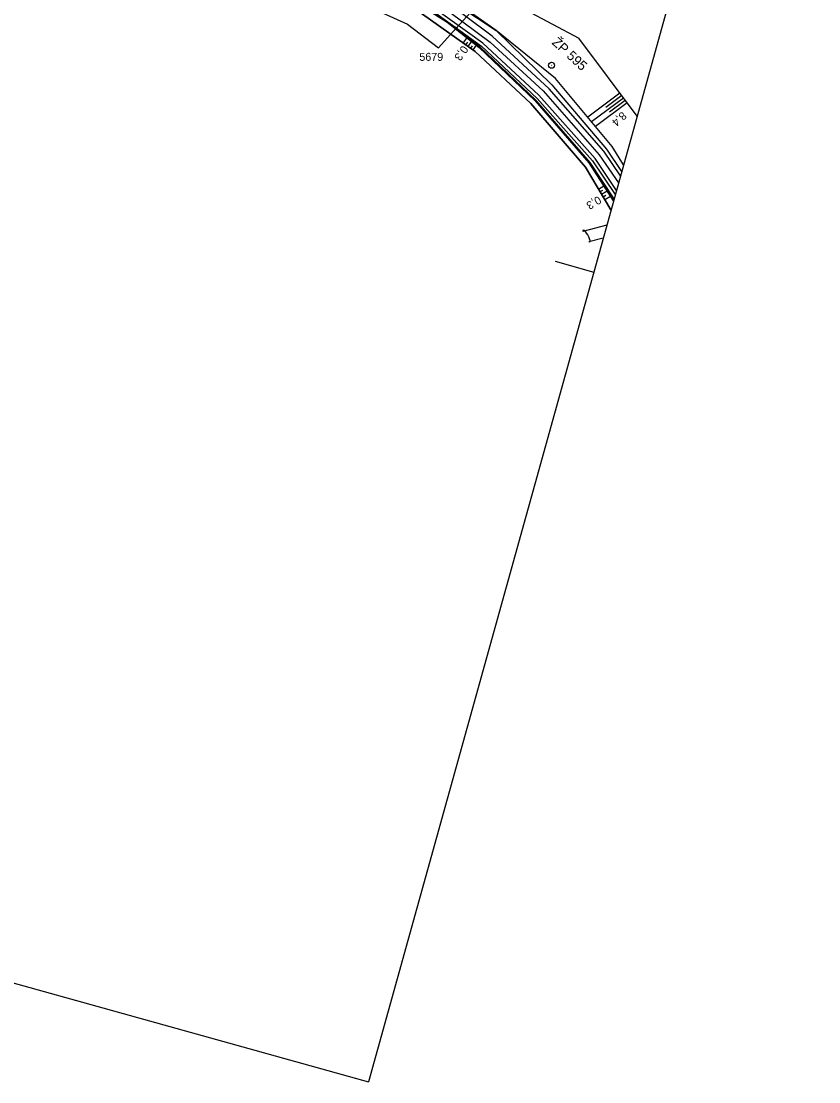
# Model space of a CAD drawing. Extents: x -795046 to -794647, y -1136002 to -1135518.
# Drawn here: x -794846.5 to -794647.1, y -1136002.2 to -1135737.2 of the extents above; entities that cross this region are included whole.
import ezdxf

# ---------------------------------------------------------------- set-up
doc = ezdxf.new("R2010")
doc.units = 0
for name, color, linetype in [('0381KM005-009P - Vrstva 1', 7, 'Continuous'), ('0381KM005-009P - Vrstva 13', 7, 'Continuous'), ('0381KM005-009P - Vrstva 18', 7, 'Continuous'), ('0381KM005-009P - Vrstva 4', 7, 'Continuous'), ('0381KM005-009P - Vrstva 48', 7, 'Continuous'), ('0381KM005-009P - Vrstva 49', 7, 'Continuous'), ('0381KM005-009P - Vrstva 51', 7, 'Continuous'), ('0381KM005-009P - Vrstva 55', 7, 'Continuous'), ('formát', 7, 'Continuous'), ('szdc - hran DP', 7, 'Continuous'), ('szdc - szdc_cislo', 7, 'Continuous'), ('szdc - szdc_krizek', 7, 'Continuous'), ('vyt_sit - stávající', 7, 'Continuous')]:
    doc.layers.add(name, color=color, linetype=linetype)

msp = doc.modelspace()

# ---------------------------------------------------------------- linework, layer by layer
at = {"layer": '0381KM005-009P - Vrstva 1'}
msp.add_lwpolyline([(-794915, -1135523.08), (-794913.46, -1135539.92), (-794911.29, -1135554.01), (-794906.18, -1135575.42), (-794898.43, -1135596.89), (-794896.25, -1135601.39), (-794889.11, -1135615.73), (-794881.58, -1135627.73), (-794877.36, -1135634.16), (-794865.05, -1135649.67), (-794850.87, -1135664.43), (-794835.06, -1135677.82), (-794817.77, -1135689.58), (-794801.57, -1135698.91), (-794785.04, -1135707.72), (-794765.11, -1135718.4), (-794746.17, -1135729.82), (-794729.27, -1135742.41), (-794716.02, -1135754.58), (-794701.99, -1135770.6), (-794697.2, -1135777.62)], dxfattribs=at)
at = {"layer": '0381KM005-009P - Vrstva 13'}
for p, q in [((-794731.96, -1135743.53), (-794740.42, -1135737.03)), ((-794740.39, -1135737.12), (-794731.99, -1135743.74)), ((-794731.99, -1135743.74), (-794718, -1135757.13)), ((-794717.76, -1135757.03), (-794731.96, -1135743.53)), ((-794718, -1135757.13), (-794704.55, -1135772.63)), ((-794704.3, -1135772.51), (-794717.76, -1135757.03)), ((-794704.55, -1135772.63), (-794698.45, -1135782.11)), ((-794698.3, -1135781.58), (-794704.3, -1135772.51)), ((-794698.45, -1135782.11), (-794698.3, -1135781.58))]:
    msp.add_line(p, q, dxfattribs=at)
at = {"layer": '0381KM005-009P - Vrstva 18'}
for p, q in [((-794700.13, -1135788.16), (-794706.12, -1135789.75)), ((-794704.6, -1135792.28), (-794701, -1135791.3))]:
    msp.add_line(p, q, dxfattribs=at)
msp.add_ellipse((-794705.21, -1135790.89), major_axis=(-0.84, 1.43), ratio=0.263257, start_param=2.714626, end_param=6.783075, dxfattribs=at)
at = {"layer": '0381KM005-009P - Vrstva 4'}
for points in [[(-794917.47, -1135522.4), (-794915.85, -1135540.59), (-794913.67, -1135554.7), (-794908.27, -1135576.33), (-794900.49, -1135597.63), (-794890.98, -1135617.37), (-794879.27, -1135635.32), (-794866.44, -1135651.71), (-794836.69, -1135679.46), (-794818.84, -1135691.63), (-794786.57, -1135709.39), (-794766.3, -1135721.02), (-794748.58, -1135730.93), (-794731.42, -1135743.47), (-794717.51, -1135756.55), (-794703.68, -1135772.07), (-794698, -1135780.52)], [(-794697.72, -1135779.5), (-794703.02, -1135771.54), (-794717.11, -1135755.66), (-794731.12, -1135742.73), (-794748.15, -1135730.35), (-794763.88, -1135720.89), (-794786.11, -1135708.79), (-794818.08, -1135691.13), (-794836.08, -1135678.99), (-794851.61, -1135665.79), (-794866.22, -1135650.67), (-794878.82, -1135634.83), (-794890.24, -1135616.8), (-794899.85, -1135597.37), (-794907.59, -1135576.09), (-794912.87, -1135554.46), (-794914.85, -1135540.94), (-794916.58, -1135522.65)], [(-794696.7, -1135775.84), (-794700.88, -1135769.71), (-794714.51, -1135754.08), (-794728.76, -1135740.91), (-794743.23, -1135730.04), (-794762.73, -1135718.04), (-794783.1, -1135707.11), (-794816.84, -1135688.49), (-794833.24, -1135677.32), (-794850.38, -1135662.96), (-794864.1, -1135648.49), (-794876.22, -1135633.13), (-794886.94, -1135616.58), (-794897.05, -1135596.51), (-794904.69, -1135574.95), (-794909.82, -1135553.82), (-794912.02, -1135540.3), (-794913.51, -1135523.5)], [(-794912.74, -1135523.71), (-794911.32, -1135540.41), (-794909.07, -1135553.52), (-794904.05, -1135574.62), (-794896.27, -1135596.21), (-794886.26, -1135616.08), (-794875.38, -1135632.64), (-794863.5, -1135647.94), (-794849.93, -1135662.35), (-794832.65, -1135676.88), (-794816.85, -1135687.92), (-794782.78, -1135706.49), (-794762.23, -1135717.77), (-794742.47, -1135729.7), (-794727.73, -1135739.54), (-794713.83, -1135753.13), (-794700.2, -1135769.22), (-794696.4, -1135774.74)]]:
    msp.add_lwpolyline(points, dxfattribs=at)
at = {"layer": '0381KM005-009P - Vrstva 48'}
for p, q in [((-794735.95, -1135742.65), (-794735, -1135741.3)), ((-794735.34, -1135743.08), (-794734.87, -1135742.42)), ((-794734.72, -1135743.51), (-794733.82, -1135742.23)), ((-794734.11, -1135743.95), (-794733.67, -1135743.32)), ((-794733.5, -1135744.38), (-794732.64, -1135743.16)), ((-794696.83, -1135755.2), (-794704.87, -1135761.2)), ((-794696.38, -1135755.8), (-794700.39, -1135758.79)), ((-794695.94, -1135756.4), (-794703.91, -1135762.35)), ((-794695.04, -1135757.6), (-794702.95, -1135763.5)), ((-794695.49, -1135757), (-794699.46, -1135759.97)), ((-794702.17, -1135779.15), (-794700.85, -1135778.36)), ((-794701.79, -1135779.79), (-794701.12, -1135779.39)), ((-794701.41, -1135780.44), (-794700.04, -1135779.62)), ((-794701.02, -1135781.08), (-794700.33, -1135780.67)), ((-794700.64, -1135781.73), (-794699.22, -1135780.89))]:
    msp.add_line(p, q, dxfattribs=at)
at = {"layer": '0381KM005-009P - Vrstva 49'}
msp.add_line((-794692.56, -1135760.93), (-794707.09, -1135741.45), dxfattribs=at)
for points in [[(-794925.83, -1135520.07), (-794923.66, -1135547.6), (-794917.9, -1135570.81), (-794907.19, -1135600.69), (-794901.33, -1135612.99), (-794892.4, -1135627.36), (-794879.19, -1135644.46), (-794863.1, -1135661.78), (-794838.91, -1135683.03), (-794815.97, -1135701.12), (-794794.79, -1135715.61), (-794782.46, -1135721.1), (-794767.75, -1135725.5), (-794750.75, -1135732.17), (-794732.98, -1135744.75), (-794719.14, -1135757.73), (-794705.45, -1135773.64), (-794699.07, -1135784.37)], [(-794889.7, -1135608.37), (-794884.32, -1135618.22), (-794824.85, -1135679.44), (-794811.36, -1135687.77), (-794786.09, -1135699.38), (-794707.09, -1135741.45)], [(-794695.93, -1135773.08), (-794698.78, -1135768.51), (-794712.94, -1135751.52), (-794727.73, -1135739.54), (-794743.72, -1135728.23), (-794763.92, -1135716.02), (-794781.48, -1135706.54), (-794800.89, -1135696.32), (-794816.57, -1135687.28), (-794832.17, -1135676.47), (-794849.4, -1135661.77), (-794863.5, -1135647.94)], [(-794698.44, -1135782.1), (-794704.53, -1135772.61), (-794717.97, -1135757.09), (-794731.96, -1135743.69), (-794740.37, -1135737.09), (-794749.75, -1135730.99)]]:
    msp.add_lwpolyline(points, dxfattribs=at)
at = {"layer": '0381KM005-009P - Vrstva 51'}
msp.add_lwpolyline([(-794699.07, -1135784.37), (-794705.45, -1135773.64), (-794719.14, -1135757.73), (-794732.98, -1135744.75), (-794750.75, -1135732.17), (-794767.75, -1135725.5), (-794782.46, -1135721.1), (-794794.79, -1135715.61), (-794815.97, -1135701.12), (-794838.91, -1135683.03), (-794863.1, -1135661.78), (-794879.19, -1135644.46), (-794892.4, -1135627.36), (-794901.33, -1135612.99), (-794907.19, -1135600.69), (-794917.9, -1135570.81), (-794923.66, -1135547.6), (-794925.83, -1135520.07)], dxfattribs=at)
at = {"layer": '0381KM005-009P - Vrstva 55'}
msp.add_lwpolyline([(-794930.32, -1135518.82), (-794928.69, -1135543.86), (-794927.18, -1135552.03), (-794921.37, -1135573.41), (-794916.26, -1135587.98), (-794906.67, -1135609.69), (-794887.27, -1135641.42), (-794862.33, -1135667.74), (-794849.1, -1135679.42), (-794837.63, -1135688.88), (-794826.42, -1135697.51), (-794808.25, -1135711.35), (-794792.02, -1135721.49), (-794781.13, -1135725.75), (-794765.57, -1135730.81), (-794749.96, -1135737.95), (-794742.14, -1135743.85), (-794737.72, -1135738.96), (-794727.83, -1135728.01), (-794718.43, -1135717.37), (-794692.54, -1135688.86), (-794715.68, -1135650.06)], dxfattribs=at)
at = {"layer": 'formát'}
for p, q in [((-794647.13, -1135597.56), (-794703.39, -1135799.88)), ((-794713.02, -1135797.2), (-794703.39, -1135799.88)), ((-794713.02, -1135797.2), (-794703.39, -1135799.88)), ((-794703.39, -1135799.88), (-794759.64, -1136002.21)), ((-795045.79, -1135922.65), (-794759.64, -1136002.21)), ((-794769.27, -1135999.53), (-794759.64, -1136002.21))]:
    msp.add_line(p, q, dxfattribs=at)
at = {"layer": 'szdc - hran DP'}
msp.add_line((-794737.72, -1135738.96), (-794755.22, -1135727.9), dxfattribs=at)
at = {"layer": 'szdc - szdc_krizek'}
for p, q in [((-794737.46, -1135739.23), (-794737.99, -1135738.7)), ((-794737.99, -1135739.23), (-794737.46, -1135738.7))]:
    msp.add_line(p, q, dxfattribs=at)
at = {"layer": 'vyt_sit - stávající'}
msp.add_line((-794713.89, -1135748.25), (-794713.97, -1135748.19), dxfattribs=at)
msp.add_circle((-794713.93, -1135748.22), 0.756, dxfattribs=at)

# ---------------------------------------------------------------- texts
at = {"layer": '0381KM005-009P - Vrstva 48'}
for s, rotation, p in [('0,3', 234.7037, (-794736.2, -1135743.12)), ('8,4', 222.8696, (-794696.3, -1135759.67)), ('0,3', 210.7283, (-794702.25, -1135780.78))]:
    msp.add_text(s, height=2, rotation=rotation, dxfattribs=at).set_placement(p)
at = {"layer": 'szdc - szdc_cislo'}
msp.add_text('5679', height=2, dxfattribs=at).set_placement((-794746.96, -1135747.11))
at = {"layer": 'vyt_sit - stávající'}
msp.add_text('ŽP 595', height=2.4, rotation=317.4103, dxfattribs=at).set_placement((-794714, -1135742.75))

doc.saveas('drawing.dxf')
